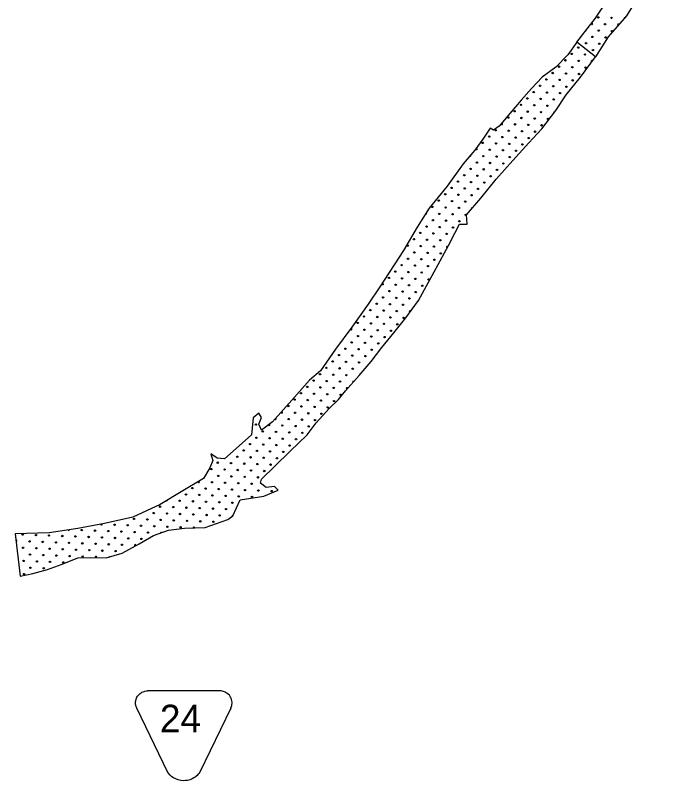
# Model space of a CAD drawing. Extents: x 1612280 to 1883141, y 560852 to 780851.
# Drawn here: x 1754954 to 1765007, y 664051 to 675742 of the extents above; entities that cross this region are included whole.
import ezdxf

# ---------------------------------------------------------------- set-up
doc = ezdxf.new("R2010")
doc.units = 0
for name, color, linetype in [('DESIGN - ROW - Easement Linework and Patterning', 7, 'Continuous'), ('DESIGN - SCRATCH - User 1', 7, 'Continuous'), ('DESIGN - TRAFFIC CONTROL PERMANENT - Pavement Marking Text', 7, 'Continuous')]:
    doc.layers.add(name, color=color, linetype=linetype)

msp = doc.modelspace()

# ---------------------------------------------------------------- linework, layer by layer
at = {"layer": 'DESIGN - ROW - Easement Linework and Patterning'}
for points in [[(1757282, 664177), (1756808, 665158), (1756797, 665185), (1756793, 665203), (1756790, 665221), (1756789, 665236), (1756790, 665254), (1756792, 665270), (1756798, 665294), (1756804, 665311), (1756812, 665327), (1756822, 665343), (1756833, 665357), (1756848, 665373), (1756862, 665385), (1756875, 665394), (1756888, 665402), (1756905, 665409), (1756920, 665415), (1756933, 665418), (1756955, 665422), (1756974, 665423)], [(1757282, 664177), (1756808, 665158), (1756797, 665185), (1756793, 665203), (1756790, 665221), (1756789, 665236), (1756790, 665254), (1756792, 665270), (1756798, 665294), (1756804, 665311), (1756812, 665327), (1756822, 665343), (1756833, 665357), (1756848, 665373), (1756862, 665385), (1756875, 665394), (1756888, 665402), (1756905, 665409), (1756920, 665415), (1756933, 665418), (1756955, 665422), (1756974, 665423)], [(1758245, 665158), (1758251, 665175), (1758259, 665198), (1758262, 665215), (1758263, 665236), (1758263, 665251), (1758261, 665269), (1758255, 665291), (1758249, 665309), (1758242, 665324), (1758233, 665339), (1758222, 665355), (1758209, 665369), (1758190, 665385), (1758176, 665395), (1758162, 665403), (1758147, 665410), (1758131, 665415), (1758111, 665420), (1758097, 665422), (1758078, 665423), (1756974, 665423)], [(1758245, 665158), (1758251, 665175), (1758259, 665198), (1758262, 665215), (1758263, 665236), (1758263, 665251), (1758261, 665269), (1758255, 665291), (1758249, 665309), (1758242, 665324), (1758233, 665339), (1758222, 665355), (1758209, 665369), (1758190, 665385), (1758176, 665395), (1758162, 665403), (1758147, 665410), (1758131, 665415), (1758111, 665420), (1758097, 665422), (1758078, 665423), (1756974, 665423)], [(1758245, 665158), (1757772, 664180), (1757756, 664160), (1757742, 664143), (1757729, 664130), (1757701, 664107), (1757679, 664093), (1757655, 664080), (1757622, 664066), (1757584, 664056), (1757552, 664052), (1757517, 664051), (1757480, 664054), (1757440, 664063), (1757404, 664077), (1757368, 664096), (1757346, 664111), (1757317, 664136), (1757282, 664177)], [(1758245, 665158), (1757772, 664180), (1757756, 664160), (1757742, 664143), (1757729, 664130), (1757701, 664107), (1757679, 664093), (1757655, 664080), (1757622, 664066), (1757584, 664056), (1757552, 664052), (1757517, 664051), (1757480, 664054), (1757440, 664063), (1757404, 664077), (1757368, 664096), (1757346, 664111), (1757317, 664136), (1757282, 664177)]]:
    msp.add_lwpolyline(points, dxfattribs=at)
at = {"layer": 'DESIGN - SCRATCH - User 1'}
for points in [[(1764719, 678692), (1764950, 678754), (1764908, 678607), (1764851, 678499), (1764842, 678329), (1764898, 678122), (1765007, 677825), (1765002, 677697), (1764955, 677391), (1764875, 677216), (1764809, 676938), (1764705, 676631), (1764597, 676296), (1764469, 676032), (1764285, 675731), (1764007, 675415), (1763813, 675109), (1763527, 675329)], [(1764719, 678692), (1764950, 678754), (1764908, 678607), (1764851, 678499), (1764842, 678329), (1764898, 678122), (1765007, 677825), (1765002, 677697), (1764955, 677391), (1764875, 677216), (1764809, 676938), (1764705, 676631), (1764597, 676296), (1764469, 676032), (1764285, 675731), (1764007, 675415), (1763813, 675109), (1763527, 675329)], [(1763527, 675329), (1763650, 675491), (1763815, 675697), (1763925, 675867), (1764045, 676083), (1764146, 676322), (1764274, 676565), (1764370, 676822), (1764503, 677097), (1764567, 677313), (1764577, 677496), (1764540, 677643), (1764471, 677831), (1764453, 677973), (1764379, 678194), (1764242, 678506)], [(1763527, 675329), (1763650, 675491), (1763815, 675697), (1763925, 675867), (1764045, 676083), (1764146, 676322), (1764274, 676565), (1764370, 676822), (1764503, 677097), (1764567, 677313), (1764577, 677496), (1764540, 677643), (1764471, 677831), (1764453, 677973), (1764379, 678194), (1764242, 678506)], [(1763813, 675108), (1763527, 675329), (1763388, 675136), (1763208, 674951), (1762998, 674796), (1762834, 674624), (1762679, 674443), (1762507, 674242), (1762344, 674049), (1762254, 673986)], [(1763813, 675108), (1763527, 675329), (1763388, 675136), (1763208, 674951), (1762998, 674796), (1762834, 674624), (1762679, 674443), (1762507, 674242), (1762344, 674049), (1762254, 673986)], [(1761843, 672693), (1762064, 672951), (1762298, 673241), (1762550, 673522), (1762793, 673795), (1762995, 674009), (1763209, 674290), (1763364, 674529), (1763582, 674798), (1763813, 675108)], [(1761843, 672693), (1762064, 672951), (1762298, 673241), (1762550, 673522), (1762793, 673795), (1762995, 674009), (1763209, 674290), (1763364, 674529), (1763582, 674798), (1763813, 675108)], [(1762254, 673986), (1762204, 674019), (1762095, 673851), (1761969, 673684), (1761793, 673474), (1761550, 673130), (1761273, 672794), (1761088, 672508), (1760879, 672147), (1760518, 671593)], [(1762254, 673986), (1762204, 674019), (1762095, 673851), (1761969, 673684), (1761793, 673474), (1761550, 673130), (1761273, 672794), (1761088, 672508), (1760879, 672147), (1760518, 671593)], [(1761109, 671383), (1761382, 671879), (1761567, 672223), (1761667, 672416), (1761734, 672550), (1761852, 672550), (1761843, 672693)], [(1761109, 671383), (1761382, 671879), (1761567, 672223), (1761667, 672416), (1761734, 672550), (1761852, 672550), (1761843, 672693)], [(1760518, 671593), (1760342, 671329), (1760094, 670976), (1759843, 670641), (1759612, 670313), (1759444, 670166), (1759218, 669910), (1758882, 669533), (1758714, 669407), (1758672, 669495), (1758714, 669596), (1758672, 669663), (1758588, 669591), (1758559, 669331), (1758328, 669125), (1758148, 668966), (1758035, 668979), (1757939, 669044)], [(1760518, 671593), (1760342, 671329), (1760094, 670976), (1759843, 670641), (1759612, 670313), (1759444, 670166), (1759218, 669910), (1758882, 669533), (1758714, 669407), (1758672, 669495), (1758714, 669596), (1758672, 669663), (1758588, 669591), (1758559, 669331), (1758328, 669125), (1758148, 668966), (1758035, 668979), (1757939, 669044)], [(1758714, 668654), (1758916, 668853), (1759150, 669083), (1759411, 669335), (1759549, 669516), (1759746, 669734), (1759889, 669873), (1759994, 670007), (1760203, 670242), (1760388, 670452), (1760551, 670666), (1760732, 670892), (1760916, 671119), (1761109, 671383)], [(1758714, 668654), (1758916, 668853), (1759150, 669083), (1759411, 669335), (1759549, 669516), (1759746, 669734), (1759889, 669873), (1759994, 670007), (1760203, 670242), (1760388, 670452), (1760551, 670666), (1760732, 670892), (1760916, 671119), (1761109, 671383)], [(1757939, 669044), (1757970, 668940), (1757924, 668831), (1757825, 668669), (1757487, 668461), (1757164, 668269), (1756748, 668076), (1756317, 667977), (1755911, 667904), (1755469, 667837), (1754954, 667821)], [(1757939, 669044), (1757970, 668940), (1757924, 668831), (1757825, 668669), (1757487, 668461), (1757164, 668269), (1756748, 668076), (1756317, 667977), (1755911, 667904), (1755469, 667837), (1754954, 667821)], [(1754954, 667821), (1755027, 667176), (1755224, 667217), (1755443, 667275), (1755667, 667358), (1755911, 667457), (1756109, 667462), (1756343, 667457), (1756587, 667524), (1756847, 667670), (1757066, 667795), (1757294, 667878), (1757539, 667910), (1757851, 667920), (1758199, 668040), (1758277, 668097), (1758387, 668341), (1758751, 668399), (1758969, 668487), (1758912, 668544), (1758782, 668529), (1758699, 668596), (1758714, 668654)], [(1754954, 667821), (1755027, 667176), (1755224, 667217), (1755443, 667275), (1755667, 667358), (1755911, 667457), (1756109, 667462), (1756343, 667457), (1756587, 667524), (1756847, 667670), (1757066, 667795), (1757294, 667878), (1757539, 667910), (1757851, 667920), (1758199, 668040), (1758277, 668097), (1758387, 668341), (1758751, 668399), (1758969, 668487), (1758912, 668544), (1758782, 668529), (1758699, 668596), (1758714, 668654)]]:
    msp.add_lwpolyline(points, dxfattribs=at)
for centre in [(1762190, 673889), (1762190, 673889), (1762391, 673881), (1762391, 673881)]:
    msp.add_circle(centre, 10.6, dxfattribs=at)
at = {"layer": 'DESIGN - TRAFFIC CONTROL PERMANENT - Pavement Marking Text'}
for centre in [(1763855, 675710), (1763855, 675710), (1763960, 675605), (1763960, 675605), (1764057, 675702), (1764057, 675702), (1763863, 675508), (1763863, 675508), (1764064, 675501), (1764064, 675501), (1763766, 675411), (1763766, 675411), (1763967, 675404), (1763967, 675404), (1763669, 675314), (1763669, 675314), (1763870, 675307), (1763870, 675307), (1763451, 675151), (1763451, 675151), (1763549, 675248), (1763549, 675248), (1763653, 675143), (1763653, 675143), (1763773, 675210), (1763773, 675210), (1763354, 675054), (1763354, 675054), (1763556, 675046), (1763556, 675046), (1763257, 674957), (1763257, 674957), (1763459, 674949), (1763459, 674949), (1763661, 674942), (1763661, 674942), (1763160, 674860), (1763160, 674860), (1763362, 674852), (1763362, 674852), (1763563, 674845), (1763563, 674845), (1763063, 674762), (1763063, 674762), (1763265, 674755), (1763265, 674755), (1763466, 674748), (1763466, 674748), (1762869, 674568), (1762869, 674568), (1762966, 674665), (1762966, 674665), (1763071, 674561), (1763071, 674561), (1763168, 674658), (1763168, 674658), (1763272, 674553), (1763272, 674553), (1763369, 674650), (1763369, 674650), (1762772, 674471), (1762772, 674471), (1762974, 674464), (1762974, 674464), (1763175, 674456), (1763175, 674456), (1762675, 674374), (1762675, 674374), (1762877, 674367), (1762877, 674367), (1763078, 674359), (1763078, 674359), (1762578, 674277), (1762578, 674277), (1762779, 674270), (1762779, 674270), (1762981, 674262), (1762981, 674262), (1762481, 674180), (1762481, 674180), (1762682, 674173), (1762682, 674173), (1762884, 674165), (1762884, 674165), (1763086, 674158), (1763086, 674158), (1762287, 673986), (1762287, 673986), (1762488, 673978), (1762488, 673978), (1762585, 674076), (1762585, 674076), (1762690, 673971), (1762690, 673971), (1762787, 674068), (1762787, 674068), (1762989, 674061), (1762989, 674061), (1762593, 673874), (1762593, 673874), (1762794, 673866), (1762794, 673866), (1762891, 673964), (1762891, 673964), (1762092, 673792), (1762092, 673792), (1762294, 673784), (1762294, 673784), (1762496, 673777), (1762496, 673777), (1762697, 673769), (1762697, 673769), (1761995, 673695), (1761995, 673695), (1762197, 673687), (1762197, 673687), (1762399, 673680), (1762399, 673680), (1762600, 673672), (1762600, 673672), (1762100, 673590), (1762100, 673590), (1762302, 673583), (1762302, 673583), (1762503, 673575), (1762503, 673575), (1761906, 673396), (1761906, 673396), (1762003, 673493), (1762003, 673493), (1762107, 673389), (1762107, 673389), (1762204, 673486), (1762204, 673486), (1762406, 673478), (1762406, 673478), (1761809, 673299), (1761809, 673299), (1762010, 673291), (1762010, 673291), (1762212, 673284), (1762212, 673284), (1762309, 673381), (1762309, 673381), (1761712, 673202), (1761712, 673202), (1761913, 673194), (1761913, 673194), (1762115, 673187), (1762115, 673187), (1761615, 673105), (1761615, 673105), (1761816, 673097), (1761816, 673097), (1762018, 673090), (1762018, 673090), (1761518, 673008), (1761518, 673008), (1761719, 673000), (1761719, 673000), (1761921, 672993), (1761921, 672993), (1761323, 672814), (1761323, 672814), (1761420, 672911), (1761420, 672911), (1761525, 672806), (1761525, 672806), (1761622, 672903), (1761622, 672903), (1761727, 672799), (1761727, 672799), (1761824, 672896), (1761824, 672896), (1761428, 672709), (1761428, 672709), (1761630, 672702), (1761630, 672702), (1761831, 672694), (1761831, 672694), (1761331, 672612), (1761331, 672612), (1761532, 672605), (1761532, 672605), (1761734, 672597), (1761734, 672597), (1761234, 672515), (1761234, 672515), (1761435, 672507), (1761435, 672507), (1761637, 672500), (1761637, 672500), (1761137, 672418), (1761137, 672418), (1761338, 672410), (1761338, 672410), (1761540, 672403), (1761540, 672403), (1760943, 672224), (1760943, 672224), (1761040, 672321), (1761040, 672321), (1761144, 672216), (1761144, 672216), (1761241, 672313), (1761241, 672313), (1761443, 672306), (1761443, 672306), (1761047, 672119), (1761047, 672119), (1761249, 672112), (1761249, 672112), (1761346, 672209), (1761346, 672209), (1761450, 672104), (1761450, 672104), (1760950, 672022), (1760950, 672022), (1761152, 672015), (1761152, 672015), (1761353, 672007), (1761353, 672007), (1760853, 671925), (1760853, 671925), (1761055, 671918), (1761055, 671918), (1761256, 671910), (1761256, 671910), (1760756, 671828), (1760756, 671828), (1760957, 671820), (1760957, 671820), (1761159, 671813), (1761159, 671813), (1760562, 671634), (1760562, 671634), (1760659, 671731), (1760659, 671731), (1760860, 671723), (1760860, 671723), (1761062, 671716), (1761062, 671716), (1761264, 671708), (1761264, 671708), (1760666, 671529), (1760666, 671529), (1760763, 671626), (1760763, 671626), (1760868, 671522), (1760868, 671522), (1760965, 671619), (1760965, 671619), (1761069, 671514), (1761069, 671514), (1761167, 671611), (1761167, 671611), (1760569, 671432), (1760569, 671432), (1760771, 671425), (1760771, 671425), (1760972, 671417), (1760972, 671417), (1760472, 671335), (1760472, 671335), (1760674, 671328), (1760674, 671328), (1760875, 671320), (1760875, 671320), (1760375, 671238), (1760375, 671238), (1760577, 671231), (1760577, 671231), (1760778, 671223), (1760778, 671223), (1760181, 671044), (1760181, 671044), (1760278, 671141), (1760278, 671141), (1760480, 671133), (1760480, 671133), (1760681, 671126), (1760681, 671126), (1760883, 671119), (1760883, 671119), (1760285, 670939), (1760285, 670939), (1760383, 671036), (1760383, 671036), (1760487, 670932), (1760487, 670932), (1760584, 671029), (1760584, 671029), (1760786, 671021), (1760786, 671021), (1760188, 670842), (1760188, 670842), (1760390, 670835), (1760390, 670835), (1760592, 670827), (1760592, 670827), (1760689, 670924), (1760689, 670924), (1760091, 670745), (1760091, 670745), (1760293, 670738), (1760293, 670738), (1760495, 670730), (1760495, 670730), (1759994, 670648), (1759994, 670648), (1760196, 670641), (1760196, 670641), (1760397, 670633), (1760397, 670633), (1759897, 670551), (1759897, 670551), (1760099, 670544), (1760099, 670544), (1760300, 670536), (1760300, 670536), (1759703, 670357), (1759703, 670357), (1759800, 670454), (1759800, 670454), (1759905, 670349), (1759905, 670349), (1760002, 670447), (1760002, 670447), (1760203, 670439), (1760203, 670439), (1759606, 670260), (1759606, 670260), (1759808, 670252), (1759808, 670252), (1760009, 670245), (1760009, 670245), (1760106, 670342), (1760106, 670342), (1759509, 670163), (1759509, 670163), (1759710, 670155), (1759710, 670155), (1759912, 670148), (1759912, 670148), (1759412, 670066), (1759412, 670066), (1759613, 670058), (1759613, 670058), (1759815, 670051), (1759815, 670051), (1759315, 669969), (1759315, 669969), (1759516, 669961), (1759516, 669961), (1759718, 669954), (1759718, 669954), (1759920, 669946), (1759920, 669946), (1759121, 669774), (1759121, 669774), (1759218, 669872), (1759218, 669872), (1759322, 669767), (1759322, 669767), (1759419, 669864), (1759419, 669864), (1759524, 669760), (1759524, 669760), (1759621, 669857), (1759621, 669857), (1759822, 669849), (1759822, 669849), (1759225, 669670), (1759225, 669670), (1759427, 669662), (1759427, 669662), (1759628, 669655), (1759628, 669655), (1759725, 669752), (1759725, 669752), (1759128, 669573), (1759128, 669573), (1759330, 669565), (1759330, 669565), (1759531, 669558), (1759531, 669558), (1758628, 669491), (1758628, 669491), (1759031, 669476), (1759031, 669476), (1759233, 669468), (1759233, 669468), (1759434, 669461), (1759434, 669461), (1758732, 669386), (1758732, 669386), (1758934, 669379), (1758934, 669379), (1759136, 669371), (1759136, 669371), (1759337, 669364), (1759337, 669364), (1758538, 669192), (1758538, 669192), (1758635, 669289), (1758635, 669289), (1758740, 669185), (1758740, 669185), (1758837, 669282), (1758837, 669282), (1758941, 669177), (1758941, 669177), (1759038, 669274), (1759038, 669274), (1759240, 669267), (1759240, 669267), (1758441, 669095), (1758441, 669095), (1758643, 669088), (1758643, 669088), (1758844, 669080), (1758844, 669080), (1759046, 669073), (1759046, 669073), (1759143, 669170), (1759143, 669170), (1758344, 668998), (1758344, 668998), (1758546, 668990), (1758546, 668990), (1758747, 668983), (1758747, 668983), (1758949, 668976), (1758949, 668976), (1758045, 668908), (1758045, 668908), (1758247, 668901), (1758247, 668901), (1758449, 668893), (1758449, 668893), (1758650, 668886), (1758650, 668886), (1758852, 668878), (1758852, 668878), (1757948, 668811), (1757948, 668811), (1758053, 668707), (1758053, 668707), (1758150, 668804), (1758150, 668804), (1758351, 668796), (1758351, 668796), (1758553, 668789), (1758553, 668789), (1758755, 668781), (1758755, 668781), (1757956, 668610), (1757956, 668610), (1758157, 668602), (1758157, 668602), (1758254, 668699), (1758254, 668699), (1758359, 668595), (1758359, 668595), (1758456, 668692), (1758456, 668692), (1758658, 668684), (1758658, 668684), (1757657, 668520), (1757657, 668520), (1757859, 668513), (1757859, 668513), (1758060, 668505), (1758060, 668505), (1758262, 668498), (1758262, 668498), (1758463, 668490), (1758463, 668490), (1758561, 668587), (1758561, 668587), (1758665, 668483), (1758665, 668483), (1758867, 668475), (1758867, 668475), (1757560, 668423), (1757560, 668423), (1757762, 668415), (1757762, 668415), (1757963, 668408), (1757963, 668408), (1758165, 668401), (1758165, 668401), (1758366, 668393), (1758366, 668393), (1758568, 668386), (1758568, 668386), (1757463, 668326), (1757463, 668326), (1757665, 668318), (1757665, 668318), (1757866, 668311), (1757866, 668311), (1758068, 668303), (1758068, 668303), (1758269, 668296), (1758269, 668296), (1757067, 668139), (1757067, 668139), (1757164, 668236), (1757164, 668236), (1757269, 668132), (1757269, 668132), (1757366, 668229), (1757366, 668229), (1757470, 668124), (1757470, 668124), (1757567, 668221), (1757567, 668221), (1757769, 668214), (1757769, 668214), (1757971, 668206), (1757971, 668206), (1758172, 668199), (1758172, 668199), (1756768, 668050), (1756768, 668050), (1756970, 668042), (1756970, 668042), (1757172, 668035), (1757172, 668035), (1757373, 668027), (1757373, 668027), (1757575, 668020), (1757575, 668020), (1757672, 668117), (1757672, 668117), (1757777, 668012), (1757777, 668012), (1757874, 668109), (1757874, 668109), (1757978, 668005), (1757978, 668005), (1758075, 668102), (1758075, 668102), (1756470, 667960), (1756470, 667960), (1756671, 667953), (1756671, 667953), (1756873, 667945), (1756873, 667945), (1757075, 667938), (1757075, 667938), (1757276, 667930), (1757276, 667930), (1757478, 667923), (1757478, 667923), (1755066, 667811), (1755066, 667811), (1755268, 667803), (1755268, 667803), (1755469, 667796), (1755469, 667796), (1755671, 667788), (1755671, 667788), (1755872, 667781), (1755872, 667781), (1755969, 667878), (1755969, 667878), (1756074, 667773), (1756074, 667773), (1756171, 667870), (1756171, 667870), (1756373, 667863), (1756373, 667863), (1756574, 667855), (1756574, 667855), (1756776, 667848), (1756776, 667848), (1756978, 667841), (1756978, 667841), (1755171, 667706), (1755171, 667706), (1755372, 667699), (1755372, 667699), (1755574, 667691), (1755574, 667691), (1755775, 667684), (1755775, 667684), (1755977, 667676), (1755977, 667676), (1756179, 667669), (1756179, 667669), (1756276, 667766), (1756276, 667766), (1756380, 667661), (1756380, 667661), (1756477, 667758), (1756477, 667758), (1756582, 667654), (1756582, 667654), (1756679, 667751), (1756679, 667751), (1756880, 667743), (1756880, 667743), (1755073, 667609), (1755073, 667609), (1755275, 667602), (1755275, 667602), (1755477, 667594), (1755477, 667594), (1755678, 667587), (1755678, 667587), (1755880, 667579), (1755880, 667579), (1756082, 667572), (1756082, 667572), (1756283, 667564), (1756283, 667564), (1756485, 667557), (1756485, 667557), (1755178, 667505), (1755178, 667505), (1755380, 667497), (1755380, 667497), (1755581, 667490), (1755581, 667490), (1755783, 667482), (1755783, 667482), (1755984, 667475), (1755984, 667475), (1755081, 667407), (1755081, 667407), (1755185, 667303), (1755185, 667303), (1755283, 667400), (1755283, 667400), (1755484, 667393), (1755484, 667393), (1755686, 667385), (1755686, 667385), (1755088, 667206), (1755088, 667206), (1755387, 667295), (1755387, 667295)]:
    msp.add_circle(centre, 10.6, dxfattribs=at)
for centre, start, end in [((1763758, 675613), 179.946, 102.7702), ((1764259, 675695), 66.8974, 210.406), ((1763661, 675516), 272.5052, 10.2109), ((1764161, 675598), 17.6612, 259.6422), ((1763758, 675039), 39.1996, 247.5936), ((1763183, 674255), 56.5647, 228.9154), ((1762384, 674083), 175.9294, 103.5224), ((1761898, 673598), 224.6646, 55.3118), ((1761226, 672717), 221.7024, 72.5193), ((1761928, 672791), 54.1061, 224.9575), ((1761547, 672201), 22.9132, 280.6833), ((1760980, 671216), 21.8273, 265.9372), ((1760084, 670947), 170.3707, 115.9267), ((1759987, 670850), 305.591, 340.7064), ((1760211, 670237), 102.5299, 174.5064), ((1760114, 670140), 52.1345, 224.3819), ((1760017, 670043), 6.0939, 270.4225), ((1759024, 669677), 163.6865, 113.0825), ((1758926, 669580), 220.5333, 56.2357), ((1758829, 669483), 169.3963, 84.3809), ((1757941, 669013), 331.8912, 61.4908), ((1757851, 668714), 243.9011, 53.1214), ((1757754, 668617), 167.52, 75.7296), ((1757261, 668333), 244.9346, 356.7514), ((1758277, 668094), 68.7552, 207.2474), ((1756268, 667967), 184.9673, 15.3969), ((1757679, 667915), 356.4201, 187.4006), ((1755768, 667885), 204.6802, 352.7215), ((1757179, 667833), 36.965, 183.026), ((1754969, 667714), 261.4625, 111.4119), ((1756783, 667646), 307.3518, 291.1779), ((1756186, 667467), 317.503, 219.9512), ((1756388, 667460), 75.4043, 135.5365)]:
    msp.add_arc(centre, 10.6, start, end, dxfattribs=at)

# ---------------------------------------------------------------- texts
at = {"layer": 'DESIGN - ROW - Easement Linework and Patterning'}
msp.add_text('24', height=422.4, rotation=0.0012, dxfattribs=at).set_placement((1757162, 664789))
msp.add_text('24', height=422.4, rotation=0.0012, dxfattribs=at).set_placement((1757162, 664789))

doc.saveas('drawing.dxf')
